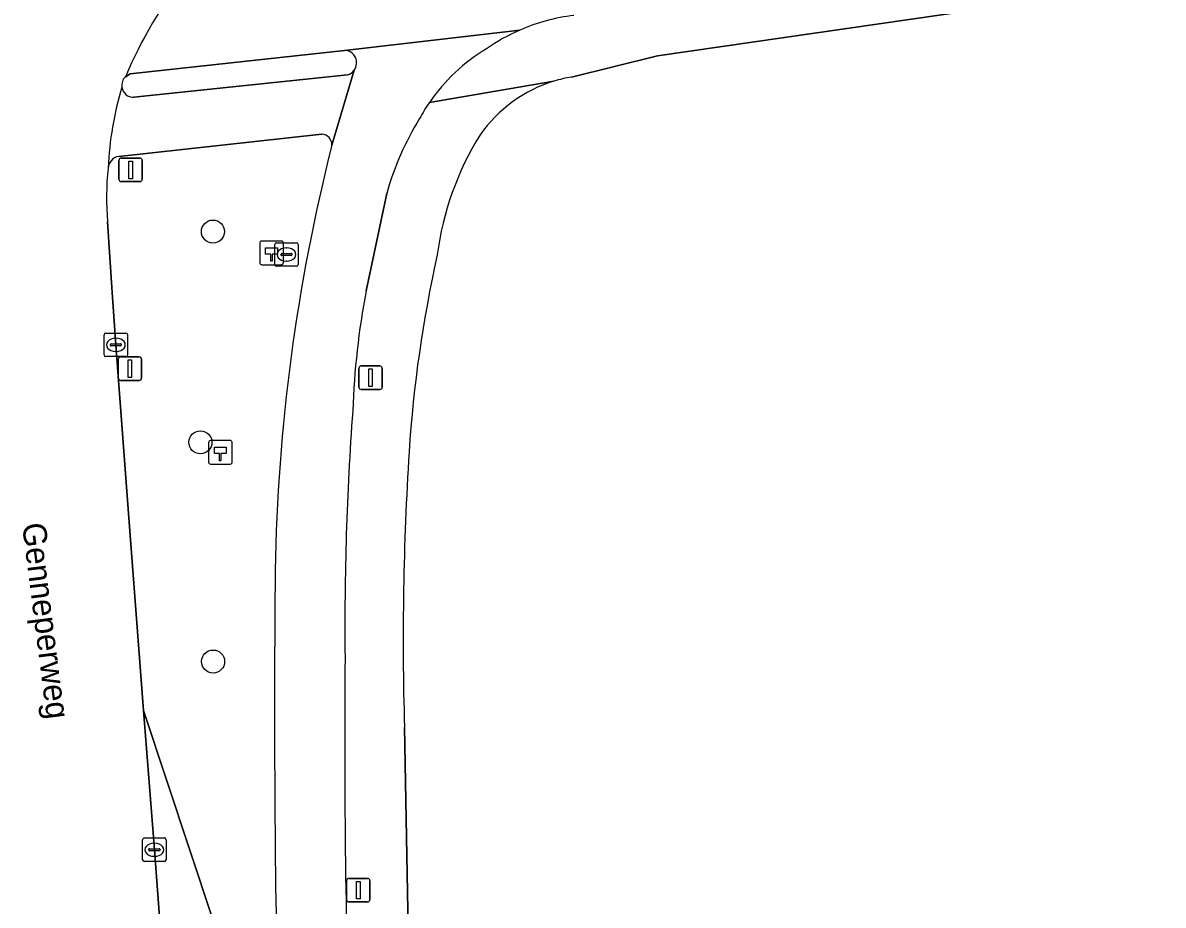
# Model space of a CAD drawing. Extents: x 160203 to 161530, y 379528 to 381797.
# Drawn here: x 160813.49 to 160861.95, y 380816.66 to 380854.19 of the extents above; entities that cross this region are included whole.
import ezdxf

# ---------------------------------------------------------------- set-up
doc = ezdxf.new("R2010")
doc.units = 0
for name, color, linetype in [('IMGEO_Berm_groen', 7, 'Continuous'), ('IMGEO_Boom', 7, 'Continuous'), ('IMGEO_Brandkraan', 7, 'Continuous'), ('IMGEO_Hectometerpaal', 7, 'Continuous'), ('IMGEO_Kolk', 7, 'Continuous'), ('IMGEO_Lichtmast', 7, 'Continuous'), ('IMGEO_Loofbos', 7, 'Continuous'), ('IMGEO_Openbare_ruimte_label', 7, 'Continuous'), ('IMGEO_Rijbaan_lokaal_gesloten', 7, 'Continuous'), ('IMGEO_Rijbaan_lokaal_open', 7, 'Continuous'), ('IMGEO_Verkeersbordpaal', 7, 'Continuous'), ('IMGEO_Verkeerseiland_open', 7, 'Continuous'), ('IMGEO_Voetpad_open', 7, 'Continuous')]:
    doc.layers.add(name, color=color, linetype=linetype)

msp = doc.modelspace()

# ---------------------------------------------------------------- linework, layer by layer
at = {"layer": 'IMGEO_Berm_groen'}
for points in [[(160826.196, 380849.447), (160817.566, 380848.504)], [(160817.095, 380845.723), (160817.287, 380842.711), (160817.446, 380840.492), (160817.997, 380833.131), (160818.626, 380824.938), (160824.542, 380807.084), (160824.325, 380812.214)]]:
    msp.add_lwpolyline(points, dxfattribs=at)
msp.add_lwpolyline([(160824.542, 380807.084), (160818.626, 380824.938), (160819.081, 380819.022), (160819.649, 380811.404), (160820.7, 380797.552), (160820.794, 380796.184), (160821.024, 380793.3), (160821.182, 380792.983), (160821.563, 380792.852), (160824.754, 380793.504), (160825.217, 380793.686), (160824.941, 380797.67)], close=True, dxfattribs=at)
for centre, radius, start, end in [((160826.178, 380849.002), 0.445, 357.9181, 87.6965), ((160903.164, 380829.603), 78.957, 165.78925, 179.08113), ((160817.645, 380847.981), 0.529, 98.5921, 177.1024), ((160828.139, 380846.759), 11.092, 173.5361, 185.3607), ((161412.084, 380824.945), 587.897, 179.422599, 181.240802)]:
    msp.add_arc(centre, radius, start, end, dxfattribs=at)
at = {"layer": 'IMGEO_Boom'}
for centre in [(160821.569, 380845.309), (160821.037, 380836.348), (160821.578, 380827.025)]:
    msp.add_circle(centre, 0.489, dxfattribs=at)
at = {"layer": 'IMGEO_Brandkraan'}
for p, q in [((160824.195, 380843.907), (160824.195, 380844.759)), ((160824.27, 380844.833), (160825.122, 380844.833)), ((160825.196, 380844.759), (160825.196, 380843.907)), ((160824.454, 380844.327), (160824.454, 380844.339)), ((160824.892, 380844.29), (160824.494, 380844.29)), ((160824.497, 380844.376), (160824.895, 380844.376)), ((160824.683, 380844.613), (160824.708, 380844.613)), ((160824.938, 380844.339), (160824.938, 380844.327)), ((160825.122, 380843.833), (160824.27, 380843.833)), ((160824.706, 380844.053), (160824.681, 380844.053))]:
    msp.add_line(p, q, dxfattribs=at)
for points in [[(160824.195, 380843.907), (160824.195, 380844.759)], [(160824.27, 380844.833), (160825.122, 380844.833)], [(160825.196, 380844.759), (160825.196, 380843.907)], [(160825.122, 380843.833), (160824.27, 380843.833)]]:
    msp.add_lwpolyline(points, dxfattribs=at)
for centre, radius, start, end in [((160824.272, 380844.757), 0.0765, 91.552, 178.448), ((160824.272, 380844.757), 0.0765, 91.552, 178.448), ((160825.12, 380844.757), 0.0765, 1.552, 88.448), ((160825.12, 380844.757), 0.0765, 1.552, 88.448), ((160824.494, 380844.336), 0.0403, 85.8775, 175.7526), ((160824.491, 380844.326), 0.0366, 178.938, 274.7102), ((160824.895, 380844.333), 0.043, 264.8664, 352.4533), ((160824.899, 380844.338), 0.0386, 1.7309, 96.639), ((160824.272, 380843.909), 0.0765, 181.552, 268.448), ((160824.272, 380843.909), 0.0765, 181.552, 268.448), ((160825.12, 380843.909), 0.0765, 271.552, 358.448), ((160825.12, 380843.909), 0.0765, 271.552, 358.448)]:
    msp.add_arc(centre, radius, start, end, dxfattribs=at)
for centre, major_axis, ratio, start_param, end_param in [((160824.682, 380844.333), (-0.387, 0.002), 0.722429, 4.712389, 7.853982), ((160824.707, 380844.333), (-0.39, 0.002), 0.717154, 1.570796, 4.712389)]:
    msp.add_ellipse(centre, major_axis=major_axis, ratio=ratio, start_param=start_param, end_param=end_param, dxfattribs=at)
at = {"layer": 'IMGEO_Hectometerpaal'}
for p, q in [((160823.561, 380844.817), (160823.561, 380843.976)), ((160823.561, 380844.817), (160823.561, 380843.976)), ((160824.477, 380844.901), (160823.636, 380844.901)), ((160824.477, 380844.901), (160823.636, 380844.901)), ((160824.561, 380843.985), (160824.561, 380844.826)), ((160824.561, 380843.985), (160824.561, 380844.826)), ((160823.645, 380843.901), (160824.486, 380843.901)), ((160823.645, 380843.901), (160824.486, 380843.901)), ((160821.385, 380836.338), (160821.385, 380835.497)), ((160821.385, 380836.338), (160821.385, 380835.497)), ((160822.301, 380836.422), (160821.46, 380836.422)), ((160822.301, 380836.422), (160821.46, 380836.422)), ((160822.385, 380835.506), (160822.385, 380836.347)), ((160822.385, 380835.506), (160822.385, 380836.347)), ((160821.469, 380835.422), (160822.31, 380835.422)), ((160821.469, 380835.422), (160822.31, 380835.422))]:
    msp.add_line(p, q, dxfattribs=at)
for points in [[(160824.086, 380844.045), (160824.026, 380844.045), (160824.026, 380844.35), (160823.806, 380844.35), (160823.806, 380844.619), (160824.306, 380844.619), (160824.306, 380844.35), (160824.086, 380844.35), (160824.086, 380844.045)], [(160821.91, 380835.566), (160821.85, 380835.566), (160821.85, 380835.871), (160821.63, 380835.871), (160821.63, 380836.14), (160822.13, 380836.14), (160822.13, 380835.871), (160821.91, 380835.871), (160821.91, 380835.566)]]:
    msp.add_lwpolyline(points, dxfattribs=at)
for centre, start, end in [((160823.639, 380844.823), 92.4484, 184.2845), ((160823.639, 380844.823), 92.4484, 184.2845), ((160824.483, 380844.823), 2.4484, 94.2845), ((160824.483, 380844.823), 2.4484, 94.2845), ((160823.639, 380843.979), 182.4484, 274.2845), ((160823.639, 380843.979), 182.4484, 274.2845), ((160824.483, 380843.979), 272.4484, 4.2845), ((160824.483, 380843.979), 272.4484, 4.2845), ((160821.463, 380836.344), 92.4484, 184.2845), ((160821.463, 380836.344), 92.4484, 184.2845), ((160822.307, 380836.344), 2.4484, 94.2845), ((160822.307, 380836.344), 2.4484, 94.2845), ((160821.463, 380835.5), 182.4484, 274.2845), ((160821.463, 380835.5), 182.4484, 274.2845), ((160822.307, 380835.5), 272.4484, 4.2845), ((160822.307, 380835.5), 272.4484, 4.2845)]:
    msp.add_arc(centre, 0.0779, start, end, dxfattribs=at)
at = {"layer": 'IMGEO_Kolk'}
for p, q in [((160816.945, 380840.066), (160816.945, 380840.918)), ((160817.02, 380840.992), (160817.872, 380840.992)), ((160817.946, 380840.918), (160817.946, 380840.066)), ((160817.204, 380840.486), (160817.204, 380840.498)), ((160817.642, 380840.449), (160817.244, 380840.449)), ((160817.247, 380840.535), (160817.645, 380840.535)), ((160817.433, 380840.772), (160817.458, 380840.772)), ((160817.688, 380840.498), (160817.688, 380840.486)), ((160817.872, 380839.992), (160817.02, 380839.992)), ((160817.456, 380840.212), (160817.431, 380840.212)), ((160818.655, 380819.522), (160819.507, 380819.522)), ((160818.58, 380818.596), (160818.58, 380819.448)), ((160818.839, 380819.016), (160818.839, 380819.028)), ((160818.882, 380819.065), (160819.28, 380819.065)), ((160819.068, 380819.302), (160819.093, 380819.302)), ((160819.323, 380819.028), (160819.323, 380819.016)), ((160819.581, 380819.448), (160819.581, 380818.596)), ((160819.507, 380818.522), (160818.655, 380818.522)), ((160819.277, 380818.979), (160818.879, 380818.979)), ((160819.091, 380818.742), (160819.066, 380818.742))]:
    msp.add_line(p, q, dxfattribs=at)
for points in [[(160816.945, 380840.066), (160816.945, 380840.918)], [(160817.02, 380840.992), (160817.872, 380840.992)], [(160817.946, 380840.918), (160817.946, 380840.066)], [(160817.872, 380839.992), (160817.02, 380839.992)], [(160818.655, 380819.522), (160819.507, 380819.522)], [(160818.58, 380818.596), (160818.58, 380819.448)], [(160819.581, 380819.448), (160819.581, 380818.596)], [(160819.507, 380818.522), (160818.655, 380818.522)]]:
    msp.add_lwpolyline(points, dxfattribs=at)
for centre, radius, start, end in [((160817.022, 380840.916), 0.0765, 91.552, 178.448), ((160817.022, 380840.916), 0.0765, 91.552, 178.448), ((160817.87, 380840.916), 0.0765, 1.552, 88.448), ((160817.87, 380840.916), 0.0765, 1.552, 88.448), ((160817.244, 380840.495), 0.0403, 85.8775, 175.7526), ((160817.241, 380840.485), 0.0366, 178.938, 274.7102), ((160817.645, 380840.492), 0.043, 264.8664, 352.4533), ((160817.649, 380840.497), 0.0386, 1.7309, 96.639), ((160817.022, 380840.068), 0.0765, 181.552, 268.448), ((160817.022, 380840.068), 0.0765, 181.552, 268.448), ((160817.87, 380840.068), 0.0765, 271.552, 358.448), ((160817.87, 380840.068), 0.0765, 271.552, 358.448), ((160818.657, 380819.446), 0.0765, 91.552, 178.448), ((160818.657, 380819.446), 0.0765, 91.552, 178.448), ((160819.505, 380819.446), 0.0765, 1.552, 88.448), ((160819.505, 380819.446), 0.0765, 1.552, 88.448), ((160818.879, 380819.025), 0.0403, 85.8775, 175.7526), ((160818.876, 380819.015), 0.0366, 178.938, 274.7102), ((160819.28, 380819.022), 0.043, 264.8664, 352.4533), ((160819.284, 380819.027), 0.0386, 1.7309, 96.639), ((160818.657, 380818.598), 0.0765, 181.552, 268.448), ((160818.657, 380818.598), 0.0765, 181.552, 268.448), ((160819.505, 380818.598), 0.0765, 271.552, 358.448), ((160819.505, 380818.598), 0.0765, 271.552, 358.448)]:
    msp.add_arc(centre, radius, start, end, dxfattribs=at)
for centre, major_axis, ratio, start_param, end_param in [((160817.432, 380840.492), (-0.387, 0.002), 0.722429, 4.712389, 7.853982), ((160817.457, 380840.492), (-0.39, 0.002), 0.717154, 1.570796, 4.712389), ((160819.067, 380819.022), (-0.387, 0.002), 0.722429, 4.712389, 7.853982), ((160819.092, 380819.022), (-0.39, 0.002), 0.717154, 1.570796, 4.712389)]:
    msp.add_ellipse(centre, major_axis=major_axis, ratio=ratio, start_param=start_param, end_param=end_param, dxfattribs=at)
at = {"layer": 'IMGEO_Lichtmast'}
for p, q in [((160817.545, 380839.079), (160817.545, 380839.879)), ((160817.545, 380839.879), (160817.545, 380839.079)), ((160817.645, 380839.979), (160818.435, 380839.979)), ((160818.435, 380839.979), (160817.645, 380839.979)), ((160818.535, 380839.879), (160818.535, 380839.079)), ((160818.535, 380839.079), (160818.535, 380839.879)), ((160827.772, 380838.692), (160827.772, 380839.492)), ((160827.772, 380839.492), (160827.772, 380838.692)), ((160827.872, 380839.592), (160828.662, 380839.592)), ((160828.662, 380839.592), (160827.872, 380839.592)), ((160828.762, 380839.492), (160828.762, 380838.692)), ((160828.762, 380838.692), (160828.762, 380839.492)), ((160818.435, 380838.979), (160817.645, 380838.979)), ((160817.645, 380838.979), (160818.435, 380838.979)), ((160828.662, 380838.592), (160827.872, 380838.592)), ((160827.872, 380838.592), (160828.662, 380838.592)), ((160827.249, 380816.902), (160827.249, 380817.702)), ((160827.249, 380817.702), (160827.249, 380816.902)), ((160827.349, 380817.802), (160828.139, 380817.802)), ((160828.139, 380817.802), (160827.349, 380817.802)), ((160828.239, 380817.702), (160828.239, 380816.902)), ((160828.239, 380816.902), (160828.239, 380817.702)), ((160828.139, 380816.802), (160827.349, 380816.802)), ((160827.349, 380816.802), (160828.139, 380816.802))]:
    msp.add_line(p, q, dxfattribs=at)
for points in [[(160817.965, 380839.854), (160818.115, 380839.854), (160818.115, 380839.104), (160817.965, 380839.104), (160817.965, 380839.854)], [(160828.192, 380839.467), (160828.342, 380839.467), (160828.342, 380838.717), (160828.192, 380838.717), (160828.192, 380839.467)], [(160827.669, 380817.677), (160827.819, 380817.677), (160827.819, 380816.927), (160827.669, 380816.927), (160827.669, 380817.677)]]:
    msp.add_lwpolyline(points, dxfattribs=at)
for centre, start, end in [((160817.645, 380839.879), 90, 180), ((160817.645, 380839.879), 90, 180), ((160818.435, 380839.879), 0, 90), ((160818.435, 380839.879), 360, 90), ((160827.872, 380839.492), 90, 180), ((160827.872, 380839.492), 90, 180), ((160828.662, 380839.492), 0, 90), ((160828.662, 380839.492), 360, 90), ((160817.645, 380839.079), 180, 270), ((160817.645, 380839.079), 180, 270), ((160818.435, 380839.079), 270, 0), ((160818.435, 380839.079), 270, 0), ((160827.872, 380838.692), 180, 270), ((160827.872, 380838.692), 180, 270), ((160828.662, 380838.692), 270, 0), ((160828.662, 380838.692), 270, 0), ((160827.349, 380817.702), 90, 180), ((160827.349, 380817.702), 90, 180), ((160828.139, 380817.702), 0, 90), ((160828.139, 380817.702), 360, 90), ((160827.349, 380816.902), 180, 270), ((160827.349, 380816.902), 180, 270), ((160828.139, 380816.902), 270, 0), ((160828.139, 380816.902), 270, 0)]:
    msp.add_arc(centre, 0.1, start, end, dxfattribs=at)
at = {"layer": 'IMGEO_Loofbos'}
for points in [[(160861.948, 380855.9), (160840.46, 380852.779), (160836.799, 380851.88)], [(160829.709, 380824.227), (160830.02, 380807.09), (160830.594, 380796.55)]]:
    msp.add_lwpolyline(points, dxfattribs=at)
for centre, radius, start, end in [((160837.817, 380845.989), 5.979, 107.0794, 144.9536), ((160837.778, 380846.139), 5.824, 99.6786, 107.1484), ((160843.755, 380842.683), 12.759, 148.1141, 172.6352), ((160884.389, 380832.43), 54.597, 167.4234, 176.3126), ((160954.942, 380827.99), 125.289, 176.3616, 181.72122)]:
    msp.add_arc(centre, radius, start, end, dxfattribs=at)
at = {"layer": 'IMGEO_Rijbaan_lokaal_gesloten'}
msp.add_lwpolyline([(160821.252, 380792.345), (160821.182, 380792.983), (160821.024, 380793.3), (160820.794, 380796.184), (160820.7, 380797.552), (160819.649, 380811.404), (160819.081, 380819.022), (160818.626, 380824.938), (160817.997, 380833.131), (160817.446, 380840.492), (160817.287, 380842.711), (160817.095, 380845.723)], dxfattribs=at)
for centre, radius, start, end in [((160835.706, 380844.361), 19.376, 141.9686, 157.123), ((160831.503, 380847.353), 14.4, 163.4456, 177.3927), ((160818.198, 380851.526), 0.504, 133.0455, 187.9786), ((160828.139, 380846.759), 11.092, 173.5361, 185.3607)]:
    msp.add_arc(centre, radius, start, end, dxfattribs=at)
at = {"layer": 'IMGEO_Rijbaan_lokaal_open'}
msp.add_lwpolyline([(160817.854, 380851.894), (160818.058, 380852.011), (160827.156, 380853.014), (160834.608, 380853.875)], dxfattribs=at)
for centre, radius, start, end in [((160835.706, 380844.361), 19.376, 141.9686, 157.123), ((160837.846, 380846.473), 8.079, 96.656, 113.6308)]:
    msp.add_arc(centre, radius, start, end, dxfattribs=at)
at = {"layer": 'IMGEO_Verkeersbordpaal'}
for p, q in [((160817.575, 380847.532), (160817.575, 380848.332)), ((160817.575, 380848.332), (160817.575, 380847.532)), ((160817.675, 380848.432), (160818.465, 380848.432)), ((160818.465, 380848.432), (160817.675, 380848.432)), ((160818.565, 380848.332), (160818.565, 380847.532)), ((160818.565, 380847.532), (160818.565, 380848.332)), ((160818.465, 380847.432), (160817.675, 380847.432)), ((160817.675, 380847.432), (160818.465, 380847.432))]:
    msp.add_line(p, q, dxfattribs=at)
msp.add_lwpolyline([(160817.995, 380848.307), (160818.145, 380848.307), (160818.145, 380847.557), (160817.995, 380847.557), (160817.995, 380848.307)], dxfattribs=at)
for centre, start, end in [((160817.675, 380848.332), 90, 180), ((160817.675, 380848.332), 90, 180), ((160818.465, 380848.332), 0, 90), ((160818.465, 380848.332), 360, 90), ((160817.675, 380847.532), 180, 270), ((160817.675, 380847.532), 180, 270), ((160818.465, 380847.532), 270, 0), ((160818.465, 380847.532), 270, 0)]:
    msp.add_arc(centre, 0.1, start, end, dxfattribs=at)
at = {"layer": 'IMGEO_Verkeerseiland_open'}
for points in [[(160827.156, 380853.014), (160818.058, 380852.011), (160817.854, 380851.894)], [(160818.212, 380851.017), (160827.283, 380851.974)]]:
    msp.add_lwpolyline(points, dxfattribs=at)
for centre, radius, start, end in [((160827.146, 380852.485), 0.529, 323.1767, 88.8647), ((160827.144, 380852.487), 0.532, 285.1966, 323.1032), ((160818.198, 380851.526), 0.504, 133.0455, 187.9786), ((160818.202, 380851.525), 0.508, 187.807, 271.0824)]:
    msp.add_arc(centre, radius, start, end, dxfattribs=at)
at = {"layer": 'IMGEO_Voetpad_open'}
for points in [[(160836.799, 380851.88), (160840.46, 380852.779), (160861.948, 380855.9)], [(160834.608, 380853.875), (160827.156, 380853.014)], [(160827.283, 380851.974), (160818.212, 380851.017)], [(160826.623, 380848.986), (160827.569, 380852.168)], [(160827.569, 380852.168), (160826.623, 380848.986)], [(160830.772, 380850.804), (160836.061, 380851.704)], [(160836.061, 380851.704), (160830.772, 380850.804)], [(160817.566, 380848.504), (160826.196, 380849.447)], [(160828.952, 380846.925), (160828.079, 380842.783)], [(160828.079, 380842.783), (160828.952, 380846.925)], [(160830.594, 380796.55), (160830.02, 380807.09), (160829.709, 380824.227)]]:
    msp.add_lwpolyline(points, dxfattribs=at)
for centre, radius, start, end in [((160837.846, 380846.473), 8.079, 96.656, 113.6308), ((160837.863, 380846.436), 8.12, 113.6309, 125.1154), ((160837.863, 380846.436), 8.12, 113.6309, 125.1154), ((160827.146, 380852.485), 0.529, 323.1767, 88.8647), ((160837.192, 380846.396), 7.788, 120.9081, 145.5289), ((160837.192, 380846.396), 7.788, 120.9081, 145.5289), ((160827.144, 380852.487), 0.532, 285.1966, 323.1032), ((160831.503, 380847.353), 14.4, 163.4456, 177.3927), ((160818.202, 380851.525), 0.508, 187.807, 271.0824), ((160837.817, 380845.989), 5.979, 107.0794, 144.9536), ((160837.778, 380846.139), 5.824, 99.6786, 107.1484), ((160837.671, 380846.111), 8.344, 145.778, 151.3494), ((160837.671, 380846.111), 8.344, 145.778, 151.3494), ((160841.083, 380843.507), 12.603, 148.3949, 164.2653), ((160841.083, 380843.507), 12.603, 148.3949, 164.2653), ((160826.178, 380849.002), 0.445, 357.9181, 87.6965), ((160843.755, 380842.683), 12.759, 148.1141, 172.6352), ((160903.164, 380829.603), 78.957, 165.78925, 179.08113), ((160817.645, 380847.981), 0.529, 98.5921, 177.1024), ((160884.389, 380832.43), 54.597, 167.4234, 176.3126), ((160861.35, 380836.488), 33.862, 169.2858, 177.9671), ((160861.35, 380836.488), 33.862, 169.2858, 177.9671), ((160952.977, 380828.551), 125.8, 175.83457, 180.61732), ((160952.977, 380828.551), 125.8, 175.83457, 180.61732), ((160954.942, 380827.99), 125.289, 176.3616, 181.72122), ((161412.084, 380824.945), 587.897, 179.422599, 181.240802), ((161212.002, 380823.493), 384.834, 179.44864, 182.048), ((161212.002, 380823.493), 384.834, 179.44864, 182.048)]:
    msp.add_arc(centre, radius, start, end, dxfattribs=at)

# ---------------------------------------------------------------- texts
at = {"layer": 'IMGEO_Openbare_ruimte_label'}
msp.add_text('Genneperweg', height=1, rotation=277.2387, dxfattribs=at).set_placement((160813.456, 380832.866))

doc.saveas('drawing.dxf')
